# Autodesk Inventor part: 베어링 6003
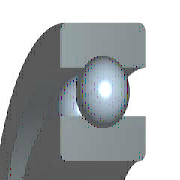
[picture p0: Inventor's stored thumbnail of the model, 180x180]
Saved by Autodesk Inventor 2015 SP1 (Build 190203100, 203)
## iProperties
IsCustomPart: 1
Company: 한국ATC센터
Created: 2014-07
Part Number: 베어링 6003
Material: 강, 연강
Description: 깊은 그루브 볼 베어링
Document SubType Name: Modeling
Standard: KS B 2023
Designer: KYOUNG IL JANG
Standards Organization: KS
Language: ko-KR
Size Designation: 6003 - 17 x 35 x 10
Categories: <MemberInstance><Categories><Category DisplayName="샤프트 부품" InternalName="7f7aeb1f-a693-4053-b835-cee3144e0d98" Mnemonic="SHFT"><Category DisplayName="베어링" Inter
Density: 1 g/cm^3
Appearance: 강철
Author: KYOUNG IL JANG
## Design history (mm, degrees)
sketch "스케치" dims "d0" = 4.68 (= -0.26 x WD + 0.26 x BD)
  geometry: L1 (2.66, 13)-(7.34, 13); L2 (5, 13)-(5, 10.66); L3 (5, 13)-(5, 15.34); L4 (3.261, 11.434)-(0, 11.434); L5 (0, 8.5)-(10, 8.5); L6 (3.261, 14.566)-(0, 14.566); L7 (0, 17.5)-(10, 17.5); L8 (10, 8.5)-(10, 11.434); L9 (6.739, 11.434)-(10, 11.434); L10 (6.739, 14.566)-(10, 14.566); L11 (10, 17.5)-(10, 14.566); L12 (-1.4, 0)-(8.4, 0) reference; L13 (0, -0.3)-(0, 5.3) reference
  constraints: 22 end point, 4 point on line, 2 collinear, 2 perpendicular, 2 symmetric about line, 1 midpoint, 1 parallel, 14 other
  dimensions: "d9" = 17 diameter of L5 L12 (= WD); "d11" = 35 diameter of L7 L12 (= BD); "d12" = 10 distance between parallel lines of L8 L13 (= KB); "d13" = 22.868 diameter of L9 L12 (= 0.326 x BD + 0.674 x WD)
revolve "본체" stored, may be unused: angle "d6" = 90 deg
revolve "볼" stored, may be unused: angle "d7" = 90 deg
pattern_circular "IDS_ARRAYBALL[SIMPL:T]" dims angle "d3" = 360 deg
body "Solid1"
fillet "모깎기1" dims "d1" = 0.3 (= KRS)
other parameters: "WD" = 17 [user parameter; used in 5 equation terms], "BD" = 35 [user parameter; used in 5 equation terms], "KB" = 10 [user parameter; used in 1 equation term], "KRS" = 0.3 [user parameter; used in 1 equation term], "d4" = 0, "d5" = 0, "d8" = 0, "d14" = 0, "d15" = 0, "BBA" = 0 [user parameter], "BC0" = 3250000 [user parameter], "BC" = 6050000 [user parameter], "BR" = 17.5 (= 0.5 x BD) [user parameter], "WR" = 8.5 (= 0.5 x WD) [user parameter]
